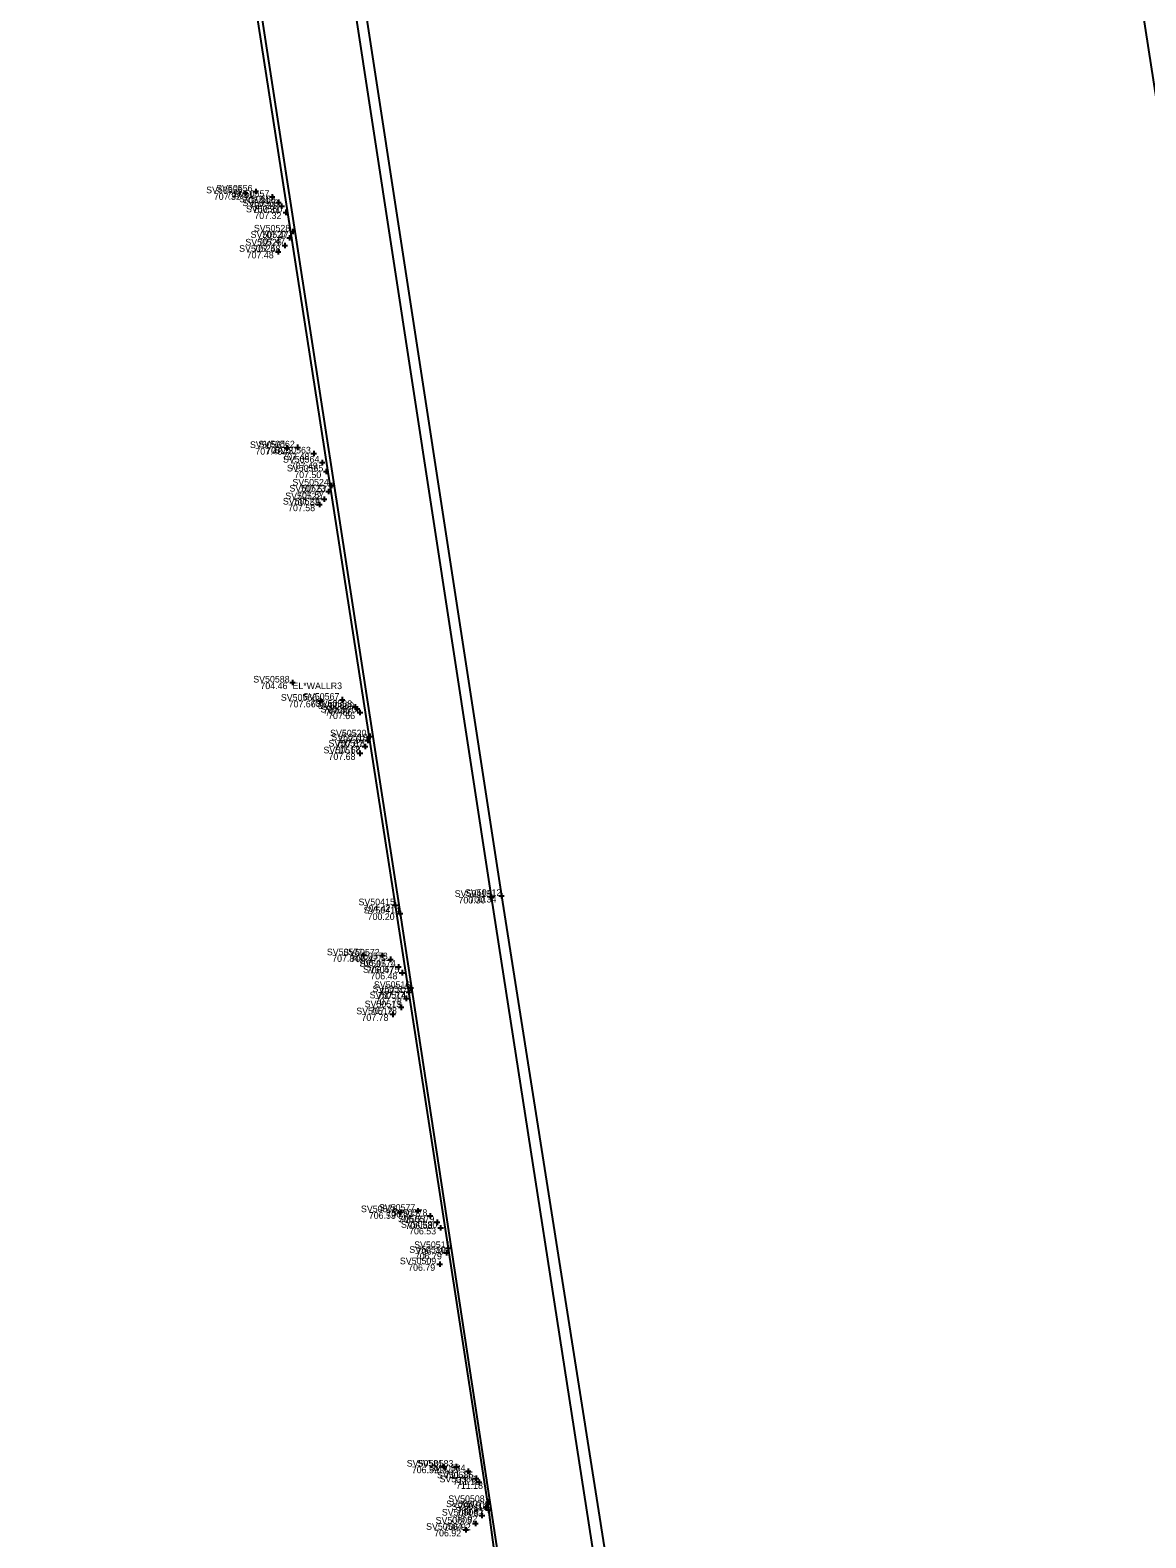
# Model space of a CAD drawing. Extents: x 182090 to 1832865, y 706265 to 714392.
# Drawn here: x 1823061.6 to 1823112.3, y 714254.3 to 714322.8 of the extents above; entities that cross this region are included whole.
import ezdxf

# ---------------------------------------------------------------- set-up
doc = ezdxf.new("R2010")
doc.units = 0
for name, color, linetype in [('BR_X_SV_Pier_Text', 7, 'Continuous'), ('PV_X_EOP', 7, 'Continuous'), ('PV_X_Shoulder', 7, 'Continuous'), ('RD_X_Wall', 7, 'Continuous'), ('SV_X_Shot_Marker', 7, 'Continuous'), ('SV_X_Text_Comment', 7, 'Continuous'), ('SV_X_Text_Elevation', 7, 'Continuous'), ('SV_X_Text_Name', 7, 'Continuous')]:
    doc.layers.add(name, color=color, linetype=linetype)

msp = doc.modelspace()

# ---------------------------------------------------------------- linework, layer by layer
at = {"layer": 'BR_X_SV_Pier_Text'}
for p, q in [((1823071.236, 714315.386), (1823071.486, 714315.386)), ((1823071.361, 714315.511), (1823071.361, 714315.261)), ((1823071.361, 714315.386), (1823071.361, 714315.386)), ((1823071.711, 714315.461), (1823071.961, 714315.461)), ((1823071.836, 714315.586), (1823071.836, 714315.336)), ((1823071.836, 714315.461), (1823071.836, 714315.461)), ((1823072.581, 714315.341), (1823072.581, 714315.091)), ((1823072.456, 714315.216), (1823072.706, 714315.216)), ((1823072.581, 714315.216), (1823072.581, 714315.216)), ((1823072.745, 714314.972), (1823072.995, 714314.972)), ((1823072.87, 714315.097), (1823072.87, 714314.847)), ((1823072.87, 714314.972), (1823072.87, 714314.972)), ((1823072.886, 714314.801), (1823073.136, 714314.801)), ((1823073.011, 714314.926), (1823073.011, 714314.676)), ((1823073.011, 714314.801), (1823073.011, 714314.801)), ((1823073.202, 714314.642), (1823073.202, 714314.392)), ((1823073.077, 714314.517), (1823073.327, 714314.517)), ((1823073.202, 714314.517), (1823073.202, 714314.517)), ((1823073.252, 714313.36), (1823073.502, 714313.36)), ((1823073.377, 714313.485), (1823073.377, 714313.235)), ((1823073.377, 714313.36), (1823073.377, 714313.36)), ((1823073.402, 714313.648), (1823073.652, 714313.648)), ((1823073.527, 714313.773), (1823073.527, 714313.523)), ((1823073.527, 714313.648), (1823073.527, 714313.648)), ((1823072.731, 714312.727), (1823072.981, 714312.727)), ((1823072.856, 714312.852), (1823072.856, 714312.602)), ((1823072.856, 714312.727), (1823072.856, 714312.727)), ((1823073.033, 714313.013), (1823073.283, 714313.013)), ((1823073.158, 714313.138), (1823073.158, 714312.888)), ((1823073.158, 714313.013), (1823073.158, 714313.013)), ((1823073.124, 714303.816), (1823073.374, 714303.816)), ((1823073.249, 714303.941), (1823073.249, 714303.691)), ((1823073.249, 714303.816), (1823073.249, 714303.816)), ((1823073.613, 714303.843), (1823073.863, 714303.843)), ((1823073.738, 714303.968), (1823073.738, 714303.718)), ((1823073.738, 714303.843), (1823073.738, 714303.843)), ((1823074.47, 714303.693), (1823074.47, 714303.443)), ((1823074.345, 714303.568), (1823074.595, 714303.568)), ((1823074.47, 714303.568), (1823074.47, 714303.568)), ((1823074.729, 714303.154), (1823074.979, 714303.154)), ((1823074.854, 714303.279), (1823074.854, 714303.029)), ((1823074.854, 714303.154), (1823074.854, 714303.154)), ((1823074.91, 714302.751), (1823075.16, 714302.751)), ((1823075.035, 714302.876), (1823075.035, 714302.626)), ((1823075.035, 714302.751), (1823075.035, 714302.751)), ((1823075.272, 714302.236), (1823075.272, 714301.986)), ((1823074.948, 714301.616), (1823074.948, 714301.366)), ((1823075.013, 714301.837), (1823075.263, 714301.837)), ((1823075.138, 714301.962), (1823075.138, 714301.712)), ((1823075.138, 714301.837), (1823075.138, 714301.837)), ((1823075.147, 714302.111), (1823075.397, 714302.111)), ((1823075.272, 714302.111), (1823075.272, 714302.111)), ((1823074.607, 714301.247), (1823074.857, 714301.247)), ((1823074.732, 714301.372), (1823074.732, 714301.122)), ((1823074.732, 714301.247), (1823074.732, 714301.247)), ((1823074.823, 714301.491), (1823075.073, 714301.491)), ((1823074.948, 714301.491), (1823074.948, 714301.491)), ((1823074.652, 714292.337), (1823074.902, 714292.337)), ((1823074.777, 714292.462), (1823074.777, 714292.212)), ((1823074.777, 714292.337), (1823074.777, 714292.337)), ((1823075.64, 714292.383), (1823075.89, 714292.383)), ((1823075.765, 714292.508), (1823075.765, 714292.258)), ((1823075.765, 714292.383), (1823075.765, 714292.383)), ((1823076.222, 714292.052), (1823076.472, 714292.052)), ((1823076.315, 714291.967), (1823076.565, 714291.967)), ((1823076.347, 714292.177), (1823076.347, 714291.927)), ((1823076.347, 714292.052), (1823076.347, 714292.052)), ((1823076.44, 714292.092), (1823076.44, 714291.842)), ((1823076.44, 714291.967), (1823076.44, 714291.967)), ((1823076.445, 714291.805), (1823076.695, 714291.805)), ((1823076.57, 714291.93), (1823076.57, 714291.68)), ((1823076.57, 714291.805), (1823076.57, 714291.805)), ((1823076.887, 714290.718), (1823077.137, 714290.718)), ((1823076.929, 714290.664), (1823076.929, 714290.414)), ((1823077.012, 714290.843), (1823077.012, 714290.593)), ((1823077.012, 714290.718), (1823077.012, 714290.718)), ((1823076.445, 714289.95), (1823076.695, 714289.95)), ((1823076.57, 714290.075), (1823076.57, 714289.825)), ((1823076.57, 714289.95), (1823076.57, 714289.95)), ((1823076.675, 714290.258), (1823076.925, 714290.258)), ((1823076.8, 714290.383), (1823076.8, 714290.133)), ((1823076.8, 714290.258), (1823076.8, 714290.258)), ((1823076.804, 714290.539), (1823077.054, 714290.539)), ((1823076.929, 714290.539), (1823076.929, 714290.539)), ((1823076.604, 714280.781), (1823076.854, 714280.781)), ((1823076.729, 714280.906), (1823076.729, 714280.656)), ((1823076.729, 714280.781), (1823076.729, 714280.781)), ((1823077.457, 714280.767), (1823077.707, 714280.767)), ((1823077.582, 714280.892), (1823077.582, 714280.642)), ((1823077.582, 714280.767), (1823077.582, 714280.767)), ((1823077.828, 714280.593), (1823078.078, 714280.593)), ((1823077.953, 714280.718), (1823077.953, 714280.468)), ((1823077.953, 714280.593), (1823077.953, 714280.593)), ((1823078.315, 714280.382), (1823078.315, 714280.132)), ((1823078.19, 714280.257), (1823078.44, 714280.257)), ((1823078.315, 714280.257), (1823078.315, 714280.257)), ((1823078.355, 714279.986), (1823078.605, 714279.986)), ((1823078.48, 714280.111), (1823078.48, 714279.861)), ((1823078.48, 714279.986), (1823078.48, 714279.986)), ((1823078.665, 714278.947), (1823078.665, 714278.697)), ((1823078.671, 714279.105), (1823078.921, 714279.105)), ((1823078.755, 714279.293), (1823079.005, 714279.293)), ((1823078.796, 714279.23), (1823078.796, 714278.98)), ((1823078.796, 714279.105), (1823078.796, 714279.105)), ((1823078.88, 714279.418), (1823078.88, 714279.168)), ((1823078.88, 714279.293), (1823078.88, 714279.293)), ((1823078.316, 714278.416), (1823078.566, 714278.416)), ((1823078.441, 714278.541), (1823078.441, 714278.291)), ((1823078.441, 714278.416), (1823078.441, 714278.416)), ((1823078.54, 714278.822), (1823078.79, 714278.822)), ((1823078.665, 714278.822), (1823078.665, 714278.822)), ((1823077.934, 714278.098), (1823078.184, 714278.098)), ((1823078.059, 714278.223), (1823078.059, 714277.973)), ((1823078.059, 714278.098), (1823078.059, 714278.098)), ((1823078.28, 714269.112), (1823078.53, 714269.112)), ((1823078.405, 714269.237), (1823078.405, 714268.987)), ((1823078.405, 714269.112), (1823078.405, 714269.112)), ((1823079.078, 714269.175), (1823079.328, 714269.175)), ((1823079.203, 714269.3), (1823079.203, 714269.05)), ((1823079.203, 714269.175), (1823079.203, 714269.175)), ((1823079.628, 714268.946), (1823079.878, 714268.946)), ((1823079.753, 714269.071), (1823079.753, 714268.821)), ((1823079.753, 714268.946), (1823079.753, 714268.946)), ((1823080.07, 714268.778), (1823080.07, 714268.528)), ((1823079.945, 714268.653), (1823080.195, 714268.653)), ((1823080.07, 714268.653), (1823080.07, 714268.653)), ((1823080.108, 714268.402), (1823080.358, 714268.402)), ((1823080.233, 714268.527), (1823080.233, 714268.277)), ((1823080.233, 714268.402), (1823080.233, 714268.402)), ((1823080.454, 714267.482), (1823080.704, 714267.482)), ((1823080.492, 714267.39), (1823080.492, 714267.14)), ((1823080.579, 714267.607), (1823080.579, 714267.357)), ((1823080.579, 714267.482), (1823080.579, 714267.482)), ((1823080.064, 714266.749), (1823080.314, 714266.749)), ((1823080.189, 714266.874), (1823080.189, 714266.624)), ((1823080.189, 714266.749), (1823080.189, 714266.749)), ((1823080.367, 714267.265), (1823080.617, 714267.265)), ((1823080.492, 714267.265), (1823080.492, 714267.265)), ((1823080.234, 714257.558), (1823080.484, 714257.558)), ((1823080.359, 714257.683), (1823080.359, 714257.433)), ((1823080.359, 714257.558), (1823080.359, 714257.558)), ((1823080.813, 714257.552), (1823081.063, 714257.552)), ((1823080.938, 714257.677), (1823080.938, 714257.427)), ((1823080.938, 714257.552), (1823080.938, 714257.552)), ((1823081.357, 714257.345), (1823081.607, 714257.345)), ((1823081.482, 714257.47), (1823081.482, 714257.22)), ((1823081.482, 714257.345), (1823081.482, 714257.345)), ((1823081.719, 714257.024), (1823081.969, 714257.024)), ((1823081.844, 714257.149), (1823081.844, 714256.899)), ((1823081.844, 714257.024), (1823081.844, 714257.024)), ((1823081.851, 714256.846), (1823082.101, 714256.846)), ((1823081.976, 714256.971), (1823081.976, 714256.721)), ((1823081.976, 714256.846), (1823081.976, 714256.846)), ((1823082.164, 714255.717), (1823082.414, 714255.717)), ((1823082.264, 714255.948), (1823082.514, 714255.948)), ((1823082.289, 714255.842), (1823082.289, 714255.592)), ((1823082.289, 714255.717), (1823082.289, 714255.717)), ((1823082.389, 714256.073), (1823082.389, 714255.823)), ((1823082.389, 714255.948), (1823082.389, 714255.948)), ((1823081.684, 714254.97), (1823081.934, 714254.97)), ((1823081.809, 714255.095), (1823081.809, 714254.845)), ((1823081.809, 714254.97), (1823081.809, 714254.97)), ((1823081.984, 714255.333), (1823082.234, 714255.333)), ((1823082.109, 714255.458), (1823082.109, 714255.208)), ((1823082.109, 714255.333), (1823082.109, 714255.333)), ((1823081.249, 714254.687), (1823081.499, 714254.687)), ((1823081.374, 714254.812), (1823081.374, 714254.562)), ((1823081.374, 714254.687), (1823081.374, 714254.687))]:
    msp.add_line(p, q, dxfattribs=at)
at = {"layer": 'PV_X_EOP'}
for points in [[(1823213.293, 713745.175), (1823205.405, 713788.669), (1823198.567, 713826.449), (1823190.488, 713870.707), (1823182.354, 713915.03), (1823174.241, 713959.25), (1823165.984, 714003.65), (1823156.504, 714055.601), (1823154.113, 714068.55), (1823146.265, 714112.428), (1823138.217, 714157.991), (1823131.409, 714200.09), (1823124.618, 714244.15), (1823117.566, 714288.492), (1823108.791, 714345.054), (1823102.174, 714389.381)], [(1823067.411, 714384.301), (1823074.33, 714339.808), (1823082.996, 714283.475), (1823089.982, 714239.194), (1823096.89, 714194.536), (1823103.258, 714152.585), (1823110.091, 714107.757), (1823116.766, 714064.256), (1823123.627, 714020.322), (1823127.152, 713997.797), (1823134.144, 713953.07), (1823140.806, 713909.017), (1823147.808, 713863.803), (1823154.619, 713819.776), (1823160.498, 713780.578), (1823166.856, 713739.218)]]:
    msp.add_lwpolyline(points, dxfattribs=at)
at = {"layer": 'PV_X_Shoulder'}
for points in [[(1823066.963, 714384.179), (1823073.884, 714339.706), (1823082.531, 714283.432), (1823089.436, 714239.039), (1823096.303, 714194.298), (1823102.729, 714152.565), (1823109.685, 714107.704), (1823116.355, 714064.136), (1823123.167, 714020.282), (1823126.577, 713997.667), (1823133.71, 713952.915), (1823140.397, 713908.841), (1823147.297, 713863.766), (1823154.059, 713819.612), (1823160.042, 713780.464), (1823166.25, 713739.132)], [(1823062.412, 714383.232), (1823069.681, 714339.147), (1823078.395, 714282.679), (1823084.433, 714243.032), (1823084.92, 714239.593), (1823085.365, 714236.389), (1823086.098, 714231.409), (1823090.212, 714205.117), (1823091.46, 714196.938), (1823091.983, 714193.775), (1823093.358, 714185.385), (1823098.276, 714152.285), (1823105.324, 714106.822), (1823112.064, 714062.977), (1823118.667, 714019.979), (1823122.178, 713997.02), (1823129.16, 713952.197), (1823135.792, 713909.032), (1823142.968, 713863.089), (1823149.523, 713818.954), (1823155.672, 713779.387), (1823161.978, 713738.44)]]:
    msp.add_lwpolyline(points, dxfattribs=at)
at = {"layer": 'RD_X_Wall'}
msp.add_lwpolyline([(1823061.595, 714383.217), (1823069.468, 714339.018), (1823078.164, 714283.052), (1823082.401, 714255.587), (1823084.562, 714239.744), (1823089.217, 714204.87), (1823096.881, 714152.352), (1823104.192, 714106.778), (1823110.948, 714062.926), (1823117.647, 714019.685), (1823121.082, 713997.094), (1823128.068, 713952.108), (1823134.675, 713909.088), (1823141.916, 713862.871), (1823148.554, 713818.502), (1823154.647, 713778.964), (1823160.909, 713738.092)], dxfattribs=at)
at = {"layer": 'SV_X_Shot_Marker'}
for p, q in [((1823073.379, 714293.166), (1823073.629, 714293.166)), ((1823073.504, 714293.291), (1823073.504, 714293.041)), ((1823073.504, 714293.166), (1823073.504, 714293.166)), ((1823078.039, 714283.052), (1823078.289, 714283.052)), ((1823078.164, 714283.177), (1823078.164, 714282.927)), ((1823078.164, 714283.052), (1823078.164, 714283.052)), ((1823082.406, 714283.432), (1823082.656, 714283.432)), ((1823082.531, 714283.557), (1823082.531, 714283.307)), ((1823082.531, 714283.432), (1823082.531, 714283.432)), ((1823082.871, 714283.475), (1823083.121, 714283.475)), ((1823082.996, 714283.6), (1823082.996, 714283.35)), ((1823082.996, 714283.475), (1823082.996, 714283.475)), ((1823078.27, 714282.679), (1823078.52, 714282.679)), ((1823078.395, 714282.804), (1823078.395, 714282.554)), ((1823078.395, 714282.679), (1823078.395, 714282.679)), ((1823082.401, 714255.712), (1823082.401, 714255.462)), ((1823082.276, 714255.587), (1823082.526, 714255.587)), ((1823082.401, 714255.587), (1823082.401, 714255.587))]:
    msp.add_line(p, q, dxfattribs=at)

# ---------------------------------------------------------------- texts
at = {"layer": 'BR_X_SV_Pier_Text'}
for s, p in [('SV50555', (1823069.585, 714315.386)), ('707.32', (1823069.934, 714315.086)), ('SV50556', (1823070.041, 714315.461)), ('707.31', (1823070.516, 714315.161)), ('SV50557', (1823070.805, 714315.216)), ('SV50558', (1823071.091, 714314.972)), ('SV50559', (1823071.232, 714314.801)), ('707.31', (1823071.261, 714314.916)), ('SV50560', (1823071.395, 714314.517)), ('707.31', (1823071.55, 714314.672)), ('707.31', (1823071.691, 714314.501)), ('SV50528', (1823071.753, 714313.648)), ('707.32', (1823071.775, 714314.217)), ('SV50526', (1823071.368, 714313.013)), ('SV50527', (1823071.605, 714313.36)), ('707.47', (1823071.95, 714313.06)), ('707.47', (1823072.1, 714313.348)), ('SV50525', (1823071.084, 714312.727)), ('707.48', (1823071.427, 714312.427)), ('707.48', (1823071.729, 714312.713)), ('SV50561', (1823071.577, 714303.816)), ('707.48', (1823071.82, 714303.516)), ('SV50562', (1823071.959, 714303.843)), ('707.48', (1823072.309, 714303.543)), ('SV50563', (1823072.689, 714303.568)), ('707.48', (1823073.041, 714303.268)), ('SV50564', (1823073.075, 714303.154)), ('SV50565', (1823073.254, 714302.751)), ('707.49', (1823073.425, 714302.854)), ('SV50524', (1823073.503, 714302.111)), ('707.50', (1823073.585, 714302.451)), ('SV50521', (1823073.07, 714301.247)), ('SV50522', (1823073.179, 714301.491)), ('SV50523', (1823073.366, 714301.837)), ('707.57', (1823073.714, 714301.537)), ('707.57', (1823073.848, 714301.811)), ('707.58', (1823073.305, 714300.947)), ('707.58', (1823073.521, 714301.191)), ('SV50566', (1823072.977, 714292.337)), ('SV50567', (1823073.984, 714292.383)), ('707.66', (1823073.329, 714292.037)), ('707.66', (1823074.317, 714292.083)), ('SV50568', (1823074.564, 714292.052)), ('SV50569', (1823074.657, 714291.967)), ('SV50570', (1823074.772, 714291.805)), ('707.66', (1823074.899, 714291.752)), ('707.66', (1823074.992, 714291.667)), ('707.66', (1823075.122, 714291.505)), ('SV50520', (1823075.214, 714290.718)), ('SV50519', (1823075.269, 714290.539)), ('707.67', (1823075.583, 714290.418)), ('SV50517', (1823074.912, 714289.95)), ('SV50518', (1823075.14, 714290.258)), ('707.68', (1823075.139, 714289.65)), ('707.68', (1823075.369, 714289.958)), ('707.67', (1823075.5, 714290.239)), ('SV50571', (1823075.067, 714280.781)), ('SV50572', (1823075.813, 714280.767)), ('707.84', (1823075.307, 714280.481)), ('706.47', (1823076.146, 714280.467)), ('SV50573', (1823076.181, 714280.593)), ('706.47', (1823076.517, 714280.293)), ('SV50574', (1823076.546, 714280.257)), ('SV50575', (1823076.708, 714279.986)), ('706.47', (1823076.879, 714279.957)), ('706.48', (1823077.042, 714279.686)), ('SV50514', (1823077.009, 714278.822)), ('SV50515', (1823077.138, 714279.105)), ('SV50516', (1823077.203, 714279.293)), ('707.77', (1823077.376, 714278.805)), ('707.77', (1823077.46, 714278.993)), ('SV50512', (1823076.403, 714278.098)), ('SV50513', (1823076.783, 714278.416)), ('707.78', (1823077.019, 714278.116)), ('707.78', (1823077.243, 714278.522)), ('707.78', (1823076.637, 714277.798)), ('SV50576', (1823076.615, 714269.112)), ('SV50577', (1823077.431, 714269.175)), ('706.53', (1823076.971, 714268.812)), ('706.53', (1823077.769, 714268.875)), ('SV50578', (1823077.979, 714268.946)), ('SV50579', (1823078.296, 714268.653)), ('706.53', (1823078.319, 714268.646)), ('SV50580', (1823078.431, 714268.402)), ('706.53', (1823078.636, 714268.353)), ('706.53', (1823078.799, 714268.102)), ('SV50510', (1823078.808, 714267.265)), ('SV50511', (1823079.03, 714267.482)), ('706.79', (1823079.148, 714267.182)), ('SV50509', (1823078.382, 714266.749)), ('706.79', (1823078.758, 714266.449)), ('706.79', (1823079.061, 714266.965)), ('SV50581', (1823078.692, 714257.558)), ('SV50583', (1823079.162, 714257.552)), ('706.59', (1823078.923, 714257.258)), ('SV50584', (1823079.708, 714257.345)), ('711.17', (1823079.892, 714257.252)), ('SV50585', (1823080.068, 714257.024)), ('SV50586', (1823080.181, 714256.846)), ('711.17', (1823080.436, 714257.045)), ('711.18', (1823080.796, 714256.724)), ('711.18', (1823080.928, 714256.546)), ('SV50507', (1823080.484, 714255.717)), ('SV50508', (1823080.582, 714255.948)), ('706.91', (1823080.96, 714255.417)), ('706.91', (1823081.06, 714255.648)), ('SV50504', (1823079.572, 714254.687)), ('SV50505', (1823080.004, 714254.97)), ('SV50506', (1823080.286, 714255.333)), ('706.92', (1823080.373, 714254.67)), ('706.92', (1823080.673, 714255.033)), ('706.92', (1823079.938, 714254.387))]:
    msp.add_text(s, height=0.3, dxfattribs=at).set_placement(p)
at = {"layer": 'SV_X_Text_Comment'}
msp.add_text('EL*WALLR3', height=0.3, dxfattribs=at).set_placement((1823073.504, 714292.866))
at = {"layer": 'SV_X_Text_Elevation'}
for s, p in [('704.46', (1823072.051, 714292.866)), ('704.42', (1823076.733, 714282.752)), ('700.30', (1823081.043, 714283.132)), ('700.34', (1823081.536, 714283.175)), ('700.20', (1823076.916, 714282.379)), ('704.37', (1823080.965, 714255.287))]:
    msp.add_text(s, height=0.3, dxfattribs=at).set_placement(p)
at = {"layer": 'SV_X_Text_Name'}
for s, p in [('SV50588', (1823071.725, 714293.166)), ('SV50413', (1823080.871, 714283.432)), ('SV50412', (1823081.338, 714283.475)), ('SV50415', (1823076.504, 714283.052)), ('SV50414', (1823076.737, 714282.679)), ('SV50416', (1823080.722, 714255.587))]:
    msp.add_text(s, height=0.3, dxfattribs=at).set_placement(p)

doc.saveas('drawing.dxf')
